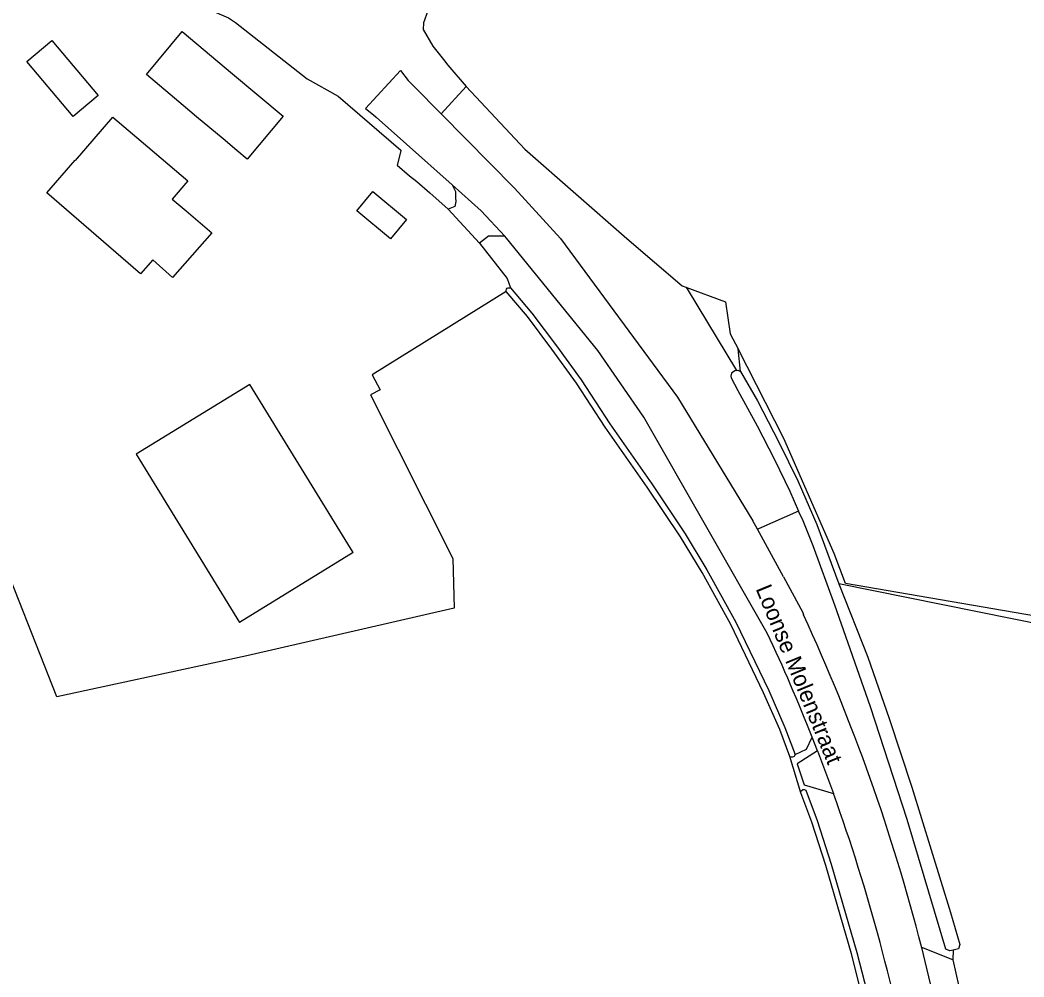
# Model space of a CAD drawing. Extents: x 134297 to 137000, y 403500 to 406000.
# Drawn here: x 134815.5 to 134969.6, y 404333.8 to 404480.7 of the extents above; entities that cross this region are included whole.
import ezdxf

# ---------------------------------------------------------------- set-up
doc = ezdxf.new("R2010")
doc.units = 0
doc.layers.add('gg-anno-openbare ruimte label', color=7, linetype='Continuous')
doc.layers.add('gx-grn-maaiveld', color=7, linetype='Continuous')

msp = doc.modelspace()

# ---------------------------------------------------------------- linework, layer by layer
at = {"layer": 'gx-grn-maaiveld'}
for p, q in [((134873.94, 404472.95), (134875.1, 404471.4)), ((134875.95, 404470.54), (134875.1, 404471.4)), ((134880.14, 404466.3), (134875.95, 404470.54)), ((134880.14, 404466.3), (134884.02, 404470.48)), ((134886.04, 404446.46), (134881.22, 404451.65)), ((134926.09, 404426.74), (134925.72, 404430.22)), ((134928.71, 404402.54), (134928, 404403.86)), ((134932.67, 404395.23), (134928.71, 404402.54)), ((134866.66, 404398.98), (134849.23, 404388.24)), ((134932.67, 404395.23), (134935.64, 404389.75)), ((134985.57, 404385.17), (134941.18, 404394.16)), ((134935.64, 404389.75), (134935.75, 404389.43)), ((134937.92, 404368.55), (134937.1, 404370.65)), ((134935.35, 404362.11), (134933.69, 404367.68)), ((134958.7, 404336.45), (134953.9, 404338.33)), ((134958.75, 404337.97), (134958.7, 404336.45)), ((134958.7, 404336.45), (134960.15, 404329.97))]:
    msp.add_line(p, q, dxfattribs=at)
for points in [[(134887.2, 404491.72), (134881.78, 404486.73), (134879.27, 404484.31), (134878.11, 404482.13), (134877.44, 404480.27), (134877.41, 404479.25), (134878.9, 404476.68), (134880.51, 404474.64), (134881.17, 404473.79), (134884.02, 404470.48)], [(134810.46, 404483.31), (134816.12, 404483.88), (134822.92, 404484.41), (134831.5, 404484.16), (134837.21, 404483.58), (134844.58, 404482.32), (134847.54, 404481.02), (134848.61, 404480.35), (134859.61, 404471.7), (134864.34, 404469), (134873.97, 404460.75), (134873.95, 404460.65), (134873.4, 404458.44), (134875.31, 404456.78), (134876.43, 404455.9), (134878.44, 404454.18), (134881.22, 404451.65)], [(134834.93, 404472.33), (134840.41, 404478.95), (134848.15, 404472.45), (134855.89, 404465.94), (134850.37, 404459.36), (134848.81, 404460.67), (134846.68, 404462.46), (134842.62, 404465.87), (134840.57, 404467.6), (134834.93, 404472.33)], [(134816.59, 404474.34), (134820.4, 404477.56), (134827.52, 404469.12), (134823.71, 404465.9), (134816.59, 404474.34)], [(134873.94, 404472.95), (134868.56, 404467.13), (134869.76, 404466.16), (134870.2, 404465.8), (134874.84, 404461.67), (134881.86, 404455.41)], [(134884.02, 404470.48), (134893.01, 404460.86), (134908.63, 404447.19), (134917.12, 404439.92), (134917.73, 404439.69)], [(134819.63, 404454.17), (134823.97, 404459.21), (134824.06, 404459.14), (134829.78, 404465.78), (134835.15, 404461.22), (134841.27, 404456.01), (134838.9, 404453.19), (134841.02, 404451.41), (134844.95, 404448.04), (134838.93, 404441.21), (134835.9, 404443.89), (134834.03, 404441.77), (134819.63, 404454.17)], [(134880.14, 404466.3), (134891.4, 404454.89), (134898.49, 404447.19), (134916.42, 404422.8), (134928, 404403.86)], [(134869.69, 404454.39), (134874.84, 404450.1), (134872.39, 404447.12), (134867.24, 404451.41), (134869.69, 404454.39)], [(134881.86, 404455.41), (134882.36, 404454.41), (134882.38, 404453.43), (134882.43, 404452.86), (134882.27, 404452.06), (134881.22, 404451.65)], [(134889.93, 404447.53), (134886.32, 404451.44), (134881.86, 404455.41)], [(134889.93, 404447.53), (134887.41, 404447.55), (134886.04, 404446.46)], [(134930.21, 404386.61), (134911.25, 404419.75), (134904.18, 404430), (134890.2, 404447.24), (134889.93, 404447.53)], [(134886.04, 404446.46), (134890.28, 404441.04), (134890.79, 404439.6)], [(134890.14, 404439.05), (134869.56, 404426.25), (134870.78, 404423.97), (134869.33, 404423.19), (134881.97, 404398.07), (134882.13, 404390.45), (134850.33, 404383.12), (134821.17, 404376.85), (134811.46, 404401.41), (134811.73, 404402.42)], [(134890.14, 404439.05), (134890.11, 404439.2), (134890.17, 404439.4), (134890.3, 404439.55), (134890.42, 404439.59), (134890.56, 404439.61), (134890.79, 404439.6)], [(134933.69, 404367.68), (134932.12, 404371.8), (134929.65, 404377.45), (134924.61, 404387.91), (134920.2, 404395.91), (134916.88, 404401.39), (134911.79, 404409.02), (134905.34, 404418.23), (134900.93, 404424.99), (134897.16, 404430.21), (134893.42, 404435.18), (134890.14, 404439.05)], [(134890.79, 404439.6), (134894.09, 404435.71), (134897.84, 404430.71), (134901.62, 404425.47), (134906.05, 404418.71), (134912.49, 404409.5), (134917.59, 404401.85), (134920.94, 404396.34), (134925.36, 404388.29), (134930.42, 404377.81), (134932.91, 404372.12), (134934.48, 404367.98)], [(134917.73, 404439.69), (134917.89, 404439.43), (134925.49, 404426.91)], [(134917.73, 404439.69), (134923.78, 404437.43), (134924.52, 404432.56), (134925.72, 404430.22)], [(134985.94, 404386.7), (134942.19, 404394.22), (134940.46, 404398.82), (134932.77, 404416.49), (134925.72, 404430.22)], [(134925.49, 404426.91), (134925.21, 404426.85), (134924.72, 404426.49), (134924.59, 404426.05), (134924.64, 404425.81), (134925.68, 404423.85), (134928.64, 404418.43), (134931.3, 404413.26), (134933.67, 404408.39), (134935.02, 404405.34)], [(134925.49, 404426.91), (134925.67, 404426.95), (134926.09, 404426.74)], [(134926.09, 404426.74), (134928.72, 404422.28), (134931.97, 404415.92), (134934.97, 404409.86), (134937.83, 404403.28), (134941.18, 404394.16)], [(134866.66, 404398.98), (134850.8, 404424.77), (134833.36, 404414.05), (134849.23, 404388.24)], [(134935.02, 404405.34), (134928.88, 404402.63), (134928.71, 404402.54)], [(134958.75, 404337.97), (134958.22, 404337.85), (134957.59, 404338.08), (134951.68, 404358.01), (134946.03, 404375.31), (134940.57, 404390.89), (134937.24, 404399.99), (134935.69, 404403.82), (134935.02, 404405.34)], [(134941.18, 404394.16), (134945.63, 404382.93), (134948.89, 404373.49), (134952.4, 404362.97), (134958.3, 404343.72), (134959.77, 404338.83), (134959.57, 404338.15), (134958.75, 404337.97)], [(134934.48, 404367.98), (134936.22, 404368.79), (134937.1, 404370.65)], [(134937.92, 404368.55), (134934.78, 404366.53), (134935.89, 404363.34), (134940.37, 404362)], [(134937.92, 404368.55), (134939.16, 404365.28), (134940.37, 404362)], [(134933.69, 404367.68), (134933.85, 404367.61), (134934.15, 404367.61), (134934.36, 404367.7), (134934.45, 404367.83), (134934.48, 404367.98)], [(134935.35, 404362.11), (134935.37, 404362.36), (134935.54, 404362.52), (134935.66, 404362.58), (134935.85, 404362.59), (134936.11, 404362.51), (134937.86, 404357.87), (134940, 404351.17), (134943.93, 404337.6), (134945.87, 404330.05), (134947.98, 404319.91), (134949.93, 404311.06), (134956.19, 404284.63), (134956.86, 404281.36), (134956.85, 404281.19), (134956.69, 404281.03), (134956.41, 404280.96), (134956.16, 404281), (134956.03, 404281.19), (134955.36, 404284.45), (134949.57, 404308.91), (134948.21, 404308.64)], [(134948.56, 404313.33), (134947.15, 404319.73), (134945.04, 404329.86), (134943.11, 404337.38), (134939.19, 404350.92), (134937.05, 404357.59), (134935.35, 404362.11)], [(134956.51, 404327.18), (134955.26, 404332.77), (134953.9, 404338.33)]]:
    msp.add_lwpolyline(points, dxfattribs=at)
for centre, radius, start, end in [((134666.89, 404265.16), 296.19, 14.302, 24.8067), ((134671.78, 404265.54), 285.38, 21.6119, 25.1021), ((134670.95, 404265.21), 286.27, 10.1726, 19.7604)]:
    msp.add_arc(centre, radius, start, end, dxfattribs=at)

# ---------------------------------------------------------------- texts
at = {"layer": 'gg-anno-openbare ruimte label'}
msp.add_text('Loonse Molenstraat', height=2.5, rotation=292.3, dxfattribs=at).set_placement((134928.39, 404393.42))

doc.saveas('drawing.dxf')
